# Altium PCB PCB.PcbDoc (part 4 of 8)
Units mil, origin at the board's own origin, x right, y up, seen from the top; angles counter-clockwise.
Board outline 11229.24 x 7764.43 mil, 14 copper layers (Top Layer, GND1, Signal 1, GND2, Signal 2, GND3, Singal 3, Power 1, GND4, Power 2, GND5, Power 3, GND6, Bottom Layer), stack 91.892 mil thick; 877 components, 305 nets, 2660 pads, 2851 vias.
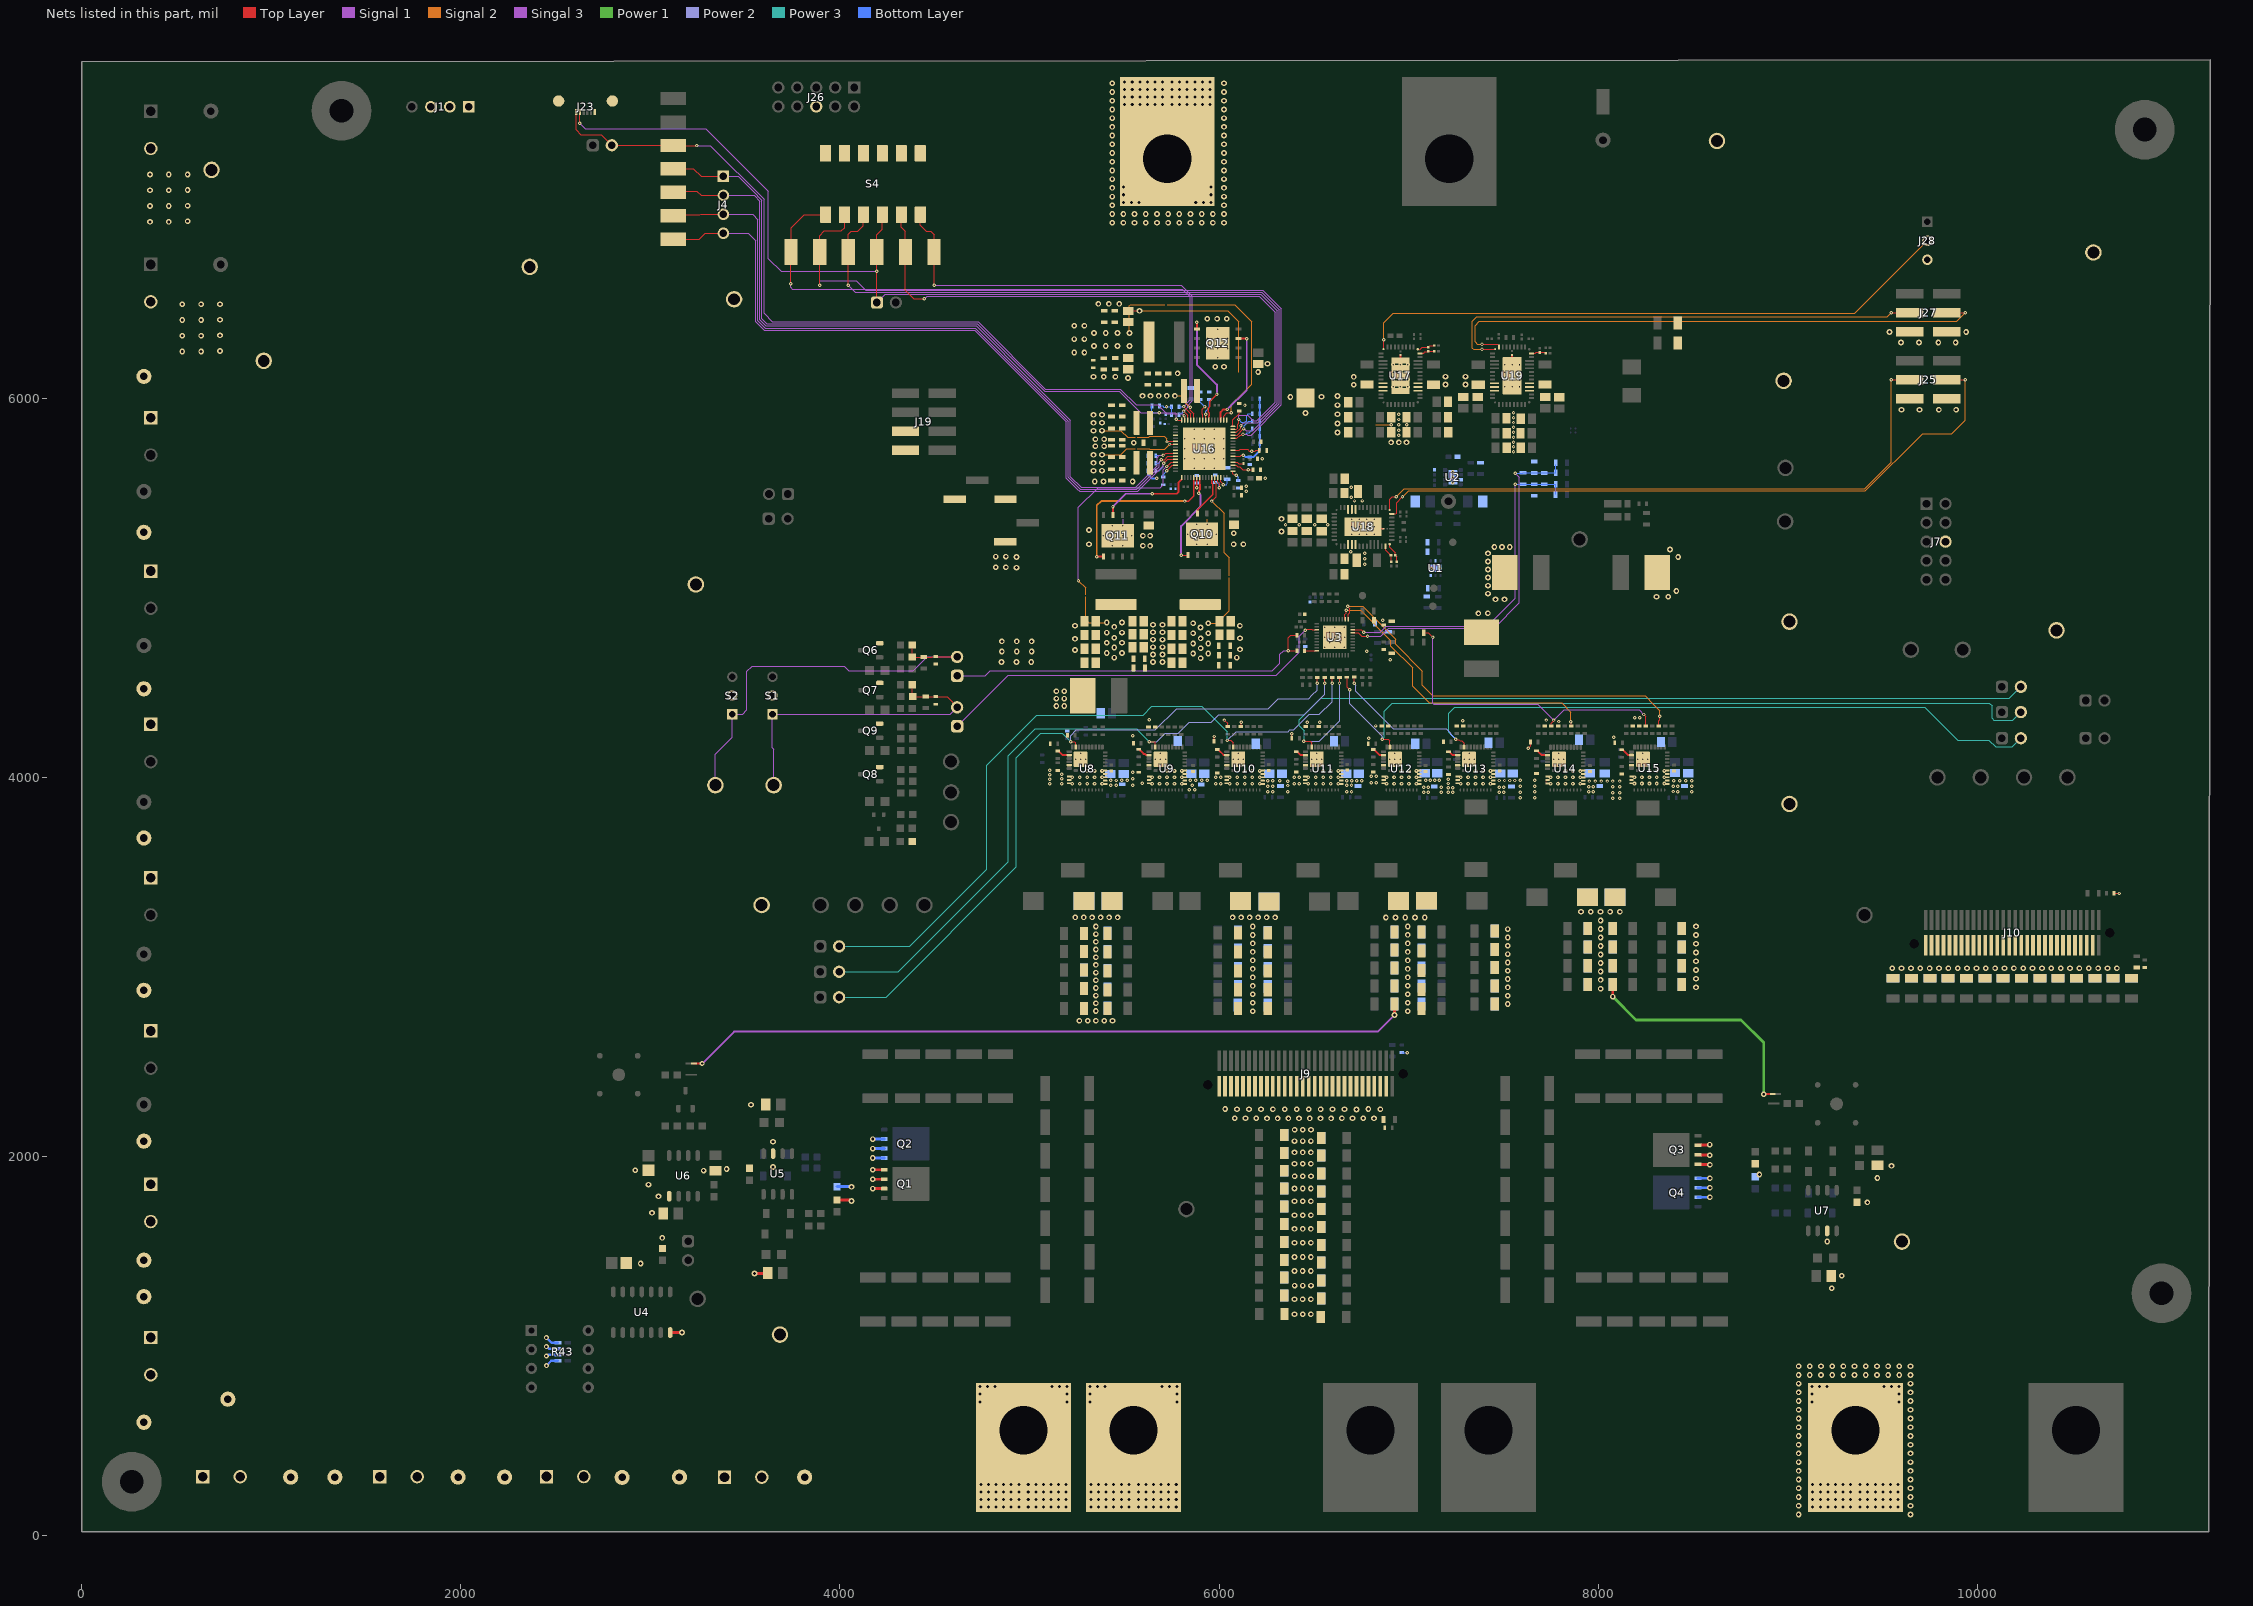
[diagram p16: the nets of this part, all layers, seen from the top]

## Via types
v1: diameter 30, hole 15, Top Layer to Bottom Layer, 1251 vias
v2: diameter 18, hole 8, Top Layer to Bottom Layer, tented both sides, 472 vias
v3: diameter 32, hole 16, Top Layer to Bottom Layer, 464 vias
v4: diameter 30, hole 15, Top Layer to Bottom Layer, tented both sides, 326 vias
v5: diameter 19.68, hole 7.87, Top Layer to Bottom Layer, 323 vias
v6: diameter 26, hole 12, Top Layer to Bottom Layer, tented both sides, 12 vias
v7: diameter 14, hole 6, Top Layer to Bottom Layer, tented both sides, 2 vias
v8: diameter 18, hole 8, Top Layer to Bottom Layer, 1 vias

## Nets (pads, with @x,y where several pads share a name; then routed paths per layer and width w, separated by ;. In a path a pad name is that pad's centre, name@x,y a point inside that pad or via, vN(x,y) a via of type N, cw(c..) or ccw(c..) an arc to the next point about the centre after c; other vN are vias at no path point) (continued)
BPWM1: R206.2 U3.1 | length 2095.7
  Top Layer w6: v2(6680.01,4902.48) 6680.01,4899.24 6689.61,4889.64 6689.61,4868.49 6681,4859.89 U3.1@6681,4832.75 ; R206.2@8320.35,4270.1 8320.35,4297.1 8325.9,4302.66 v2(8325.9,4322.06)
  Signal 2 w6: v2(6680.01,4902.48) 6758.53,4902.48 6932.22,4728.79 6932.22,4700.48 7072.8,4559.9 7072.8,4484.4 7127.96,4429.25 8247.76,4429.25 8290.66,4386.34 8325.9,4351.11 v2(8325.9,4322.06)
BPWM2: R198.2 U3.2 | length 1609.4
  Top Layer w6: U3.2@6665.25,4832.75 6664.32,4833.69 6664.32,4859.71 6669.97,4865.36 v2(6669.97,4881.79) ; v2(7856.1,4292.8) 7858.3,4290.6 R198.2@7858.3,4270.1
  Signal 2 w6: v2(6669.97,4881.79) 6746.62,4881.79 6906.93,4721.48 6906.93,4691.28 7021.38,4576.83 7021.38,4480.41 7109.49,4392.3 7807.46,4392.3 7856.1,4343.66 v2(7856.1,4292.8)
BTAO: R25.2 R201.1 R209.1 | length 1691.9
  Top Layer w6: R25.2@7079.59,4763.14 7103.7,4763.14 v2(7128.58,4738.26) ; R201.1@7753.45,4270.1 7753.45,4285.74 7766.36,4298.65 v2(7766.36,4301.9) ; v2(8240.96,4331.09) 8251.2,4320.86 R209.1@8251.2,4270.1
  Signal 1 w6: v2(7128.58,4738.26) 7128.58,4389.21 7132.09,4385.7 7682.56,4385.7 v2(7766.36,4301.9) 7820.36,4355.9 8216.16,4355.9 v2(8240.96,4331.09)
BUCK1_OUT: C309.1 C310.1 C311.1 C312.1 C313.1 C314.2 C315.2 C316.1 C398.1 J14.2 J19.5 J19.7 L11.2 NT10.2 TP49.1 | length 238.1
  Signal 2 w6: NT10.2@5295.9,4952.3 5295.9,4832.78 5312.33,4816.35 v1(5407.7,4816.35)
  other v1: 5447.4,4631.15 5407.7,4656.02 5487.8,4656.02 5447.4,4684.36 5407.7,4709.46 5487.8,4709.46 5447.4,4736.33 5407.7,4762.91 5487.8,4762.91 5447.05,4793.38 5487.8,4816.35
  other v4: 4852.6,4607.8 4931.1,4607.8 5009.6,4607.8 4854.2,4663.5 4932.7,4663.5 5011.2,4663.5 4854.2,4717 4932.7,4717 5011.2,4717
BUCK2_OUT: C319.2 C320.1 C321.1 C322.2 C323.2 C324.2 C325.1 J15.2 L12.2 NT12.2 TP51.1 | length 331.3
  Signal 2 w6: v1(5527.1,6344.1) 5527.1,6487.47 5533.13,6493.5 NT12.2@5712.57,6493.5
  other v1: 5235.8,6240.7 5289.3,6240.7 5340.04,6275.26 5402.39,6275.26 5464.75,6275.26 5527.1,6275.26 5235.85,6311.55 5289.35,6311.55 5340.04,6344.1 5402.39,6344.1 5464.75,6344.1 5235.85,6382.4 5289.35,6382.4
BUCK3_OUT: C326.2 C327.2 C328.2 J16.2 L13.2 NT13.2 TP53.1 | length 62.7
  Signal 2 w6: v4(5766.82,6012) 5816.08,6012 5819.6,6008.49 NT13.2@5819.6,5999.97
  other v4: 5596.18,6012 5638.84,6012 5681.5,6012 5724.16,6012
BUCK4_OUT: C329.1 C330.1 C331.2 C332.2 J17.2 L14.2 NT14.2 TP55.1 | length 187.9
  Signal 2 w6: v4(5382.2,5701.72) 5481.32,5701.72 5512.06,5732.45 NT14.2@5557.4,5732.45
  other v4: 5337.4,5616.68 5382.2,5617.48 5337.4,5658.8 5382.2,5659.6 5337.4,5700.92
BUCK5_OUT: C333.2 C334.2 C335.2 C396.2 J18.2 L15.2 NT15.2 TP57.1 | length 190.1
  Signal 2 w6: v4(5382.2,5828.48) 5481.62,5828.48 5517.6,5792.5 NT15.2@5557.4,5792.5
  other v4: 5337.4,5827.68 5337.4,5869.8 5382.2,5870.6 5337.4,5911.92 5382.2,5912.72
BUCK6_OUT: C301.1 C302.1 C303.1 C304.2 C305.2 C306.1 C339.1 C399.1 C400.1 C401.2 J13.2 J20.1 J21.1 J22.1 L10.2 NT8.2 TP47.1 U16.46 | length 403.4
  Top Layer w6: U16.46@6008.4,5580.87 6008.4,5558.14 v2(6022.4,5544.14)
  Signal 2 w6: v1(5943.32,4812.9) 5988.82,4812.9 6053.81,4877.89 NT8.2@6053.81,5053.82
  Bottom Layer w6: v2(6022.4,5544.14) 6040.13,5544.14 6043.65,5547.66 C339.1@6043.65,5572.45
  other v1: 5902.92,4627.7 5863.22,4652.57 5943.32,4652.57 5902.92,4680.91 5863.22,4706.01 5943.32,4706.01 5902.92,4732.88 5863.22,4759.45 5943.32,4759.45 5902.57,4789.93 5863.22,4812.9
  other v4: 4931.1,5106.1 4821.9,5107.7 4875.4,5107.7 4931.1,5162.5 4821.9,5164.1 4875.4,5164.1
BVR_EN: R20.2 U3.20 | length 64.5
  Top Layer w6: R20.2@6451.59,4667.4 6514.5,4667.4 U3.20@6515.6,4666.3
CTL1: R220.1 S4.1 TP63.1 U16.13 | length 3358.8
  Top Layer w6: v2(3740.1,6604.2) 3740.1,6769.2 TP63.1@3742.07,6771.17 3742.07,6899.37 3810.5,6967.8 S4.1@3924.11,6967.8 ; v2(5813.2,5955.83) 5813.2,5955.15 5850.92,5917.42 U16.13@5850.92,5884.02
  Singal 3 w6: v2(3740.1,6604.2) 3740.1,6585 3749.5,6575.6 5806,6575.6 5847.74,6533.86 5847.74,5990.37 v2(5813.2,5955.83)
  Bottom Layer w6: R220.1@5788.83,5955.23 5789.43,5955.83 v2(5813.2,5955.83)
CTL2: R219.1 S4.2 TP62.1 U16.60 | length 3901
  Top Layer w6: v2(3892.99,6595.3) 3892.99,6857.69 3917.6,6882.3 4007.04,6882.3 4024.11,6899.37 S4.2@4024.11,6967.8 ; U16.60@6073.37,5787.57 6094.56,5787.57 6111.09,5804.1 6117.28,5804.1 6123.09,5809.91 v2(6126.34,5809.91)
  Signal 1 w6: v2(3892.99,6595.3) 3892.99,6615.99 3896.51,6619.5 4086,6619.5 4135.3,6570.2 6230.31,6570.2 6329,6471.51 6329,5965.09 6169.16,5805.25 6151.7,5805.25 6147.04,5809.91 v2(6126.34,5809.91)
  Bottom Layer w6: v2(6126.34,5809.91) 6140.59,5809.91 6149.11,5818.43 6159.24,5818.43 6174.8,5833.99 R219.1@6174.8,5838.49
CTL3/SLPENB1: R218.1 S4.3 TP61.1 U16.61 | length 3640.9
  Top Layer w6: v2(4043.92,6595.3) 4043.92,6863.82 4059.7,6879.6 4094.83,6879.6 4124.11,6908.89 S4.3@4124.11,6967.8 ; U16.61@6073.37,5803.32 6094.75,5803.32 6128.88,5837.45 v2(6130.3,5837.45)
  Signal 1 w6: v2(4043.92,6595.3) 4080.02,6559.2 6225.76,6559.2 6318,6466.96 6318,5969.65 6177.04,5828.69 6142.3,5828.69 6133.55,5837.45 v2(6130.3,5837.45)
  Bottom Layer w6: v2(6130.3,5837.45) 6132.6,5839.74 6132.6,5853.36 6157.23,5877.99 R218.1@6174.8,5877.99
CTL4: J23.5 J24.1 S4.4 TP65.1 U16.62 | length 5591.9
  Top Layer w6: v2(2628.17,7449.22) J23.5@2628.17,7508.58 ; J24.1@4195.1,6504.5 4195.1,6770.91 TP65.1@4194.84,6771.17 4194.84,6862.54 4224.11,6891.81 S4.4@4224.11,6967.8 ; U16.62@6073.37,5819.06 6073.54,5819.24 6091.76,5819.24 6113.3,5840.78 6113.3,5852.84 v2(6115.6,5855.13)
  Signal 1 w6: J24.1@4195.1,6504.5 4238.8,6548.2 6221.2,6548.2 6307,6462.4 6307,5974.21 6203.39,5870.6 6131.07,5870.6 v2(6115.6,5855.13)
  Singal 3 w6: v2(2628.17,7449.22) 2656.49,7420.9 3292.76,7420.9 3621.5,7092.16 3621.5,6736.5 3689.2,6668.8 v2(4194.84,6668.8)
CTL5: R217.1 S4.5 TP64.1 U16.63 | length 3347.9
  Top Layer w6: S4.5@4324.11,6967.8 4324.11,6901.25 4345.76,6879.6 TP64.1@4345.76,6771.17 4343.8,6769.22 4343.8,6568.1 4388.3,6523.6 v2(4444.3,6523.6) ; U16.63@6073.37,5834.81 6091.78,5834.81 6098.6,5841.63 6098.6,5862.13 6102.92,5866.45 v2(6102.92,5887.56)
  Signal 1 w6: v2(4444.3,6523.6) 4445.88,6523.6 4459.48,6537.2 6211.46,6537.2 6296,6452.66 6296,5978.76 6198.84,5881.6 6180.26,5881.6 6152.16,5909.7 6106.43,5909.7 6102.92,5906.19 v2(6102.92,5887.56)
  Bottom Layer w6: v2@6102.96,5887.56 6118.38,5872.13 6135.82,5872.13 6145.14,5881.46 6145.14,5907.65 6154.98,5917.48 R217.1@6174.8,5917.48
CTL6/SLPENB2: R216.1 S4.6 TP66.1 U16.14 | length 2513.5
  Top Layer w6: S4.6@4424.11,6967.8 4424.11,6911.39 4455.9,6879.6 4479.62,6879.6 4496.68,6862.54 TP66.1@4496.68,6771.17 v2(4496.7,6595.3) ; v2(5813.69,5932.02) 5835.18,5910.54 U16.14@5835.18,5884.02
  Singal 3 w6: v2(4496.7,6595.3) 5801.86,6595.3 5858.74,6538.42 5858.74,5985.81 5833.74,5960.81 5833.74,5952.07 v2(5813.69,5932.02)
  Bottom Layer w6: R216.1@5788.83,5920.79 5802.45,5920.79 v2(5813.69,5932.02)
DRVH1: Q11.3 U16.33 | length 495.8
  Top Layer w10: Q11.3@5440.35,5384.05 v2(5440.35,5427.56) ; v2(5647,5495.8) 5777.73,5495.8 5785.4,5503.47 5785.4,5554.88 U16.33@5802.62,5572.09
  Signal 1 w10: v2(5440.35,5427.56) 5508.59,5495.8 v2(5647,5495.8)
DRVH2: Q12.3 U16.3 | length 542.7
  Top Layer w10: U16.3@6008.4,5884.02 6008.4,5926.2 6022.5,5940.3 v2(6043.65,5940.3) ; Q12.3@6103.3,6314.17 v2(6146.32,6314.17)
  Signal 1 w10: v2(6043.65,5940.3) 6146.32,6042.97 v2(6146.32,6314.17)
DRVH6: Q10.3 U16.43 | length 226
  Top Layer w8: Q10.3@5885.18,5391.85 5887.67,5394.35 5887.67,5413.21 5967.8,5493.34 5967.8,5544.6 5961.16,5551.24 U16.43@5961.16,5580.87
DRVL1: Q11.5 U16.37 | length 934.9
  Top Layer w6: Q11.5@5390.27,5163.9 Q11.5@5390.35,5163.97
  Top Layer w8: v2(5819.35,5457.4) 5840.04,5457.4 5866.67,5484.03 U16.37@5866.67,5580.87
  Top Layer w10: v2(5354.9,5163.9) Q11.5@5390.27,5163.9
  Signal 2 w10: v2(5354.9,5163.9) 5354.9,5433.9 5378.4,5457.4 v2(5819.35,5457.4)
DRVL2: Q12.5 U16.7 | length 620
  Top Layer w8: U16.7@5945.41,5884.02 5945.48,5884.09 5945.48,5904.82 5947.6,5906.94 5947.6,5922.74 5943.16,5927.18 5943.16,5946.88 5951.95,5955.67 5951.95,5983.64 v2(5988.98,6020.67)
  Top Layer w10: Q12.5@5883.22,6364.17 v2(5883.22,6401.34)
  Signal 1 w10: v2(5883.22,6401.34) 5883.22,6176.78 5988.98,6071.02 v2(5988.98,6020.67)
DRVL6: Q10.5 U16.39 | length 494
  Top Layer w6: v2(5799.73,5171.7) Q10.5@5835.1,5171.7
  Top Layer w10: v2(5892.6,5498.53) 5894.13,5500.06 5894.13,5512.78 5899.42,5518.07 5899.42,5544.91 5898.17,5546.16 U16.39@5898.17,5580.87
  Signal 1 w10: v2(5799.73,5171.7) 5799.73,5325.31 5902.92,5428.5 5902.92,5488.21 v2@5893.24,5497.89
EN1_YES_1: J25.3 U18.1 | length 3315
  Top Layer w6: U18.1@6900.12,5410 6900.71,5410.6 6900.71,5466.21 6914.27,5479.77 v2(6935.63,5479.77) ; v2(9546.3,6096.9) J25.3@9643.46,6096.9
  Signal 2 w6: v2(6935.63,5479.77) 6977.56,5521.7 9405.6,5521.7 9546.3,5662.4 v2(9546.3,6096.9)
EN1_YES_2: J27.3 U19.1 | length 2590.1
  Top Layer w6: v2(7387.16,6257.85) 7387.41,6258.1 7456.12,6258.1 U19.1@7456.37,6258.34 ; v2(9546.3,6450.6) J27.3@9643.46,6450.6
  Signal 2 w6: v2(7387.16,6257.85) 7342.95,6257.85 7336.2,6264.6 7336.2,6405.7 7358.8,6428.3 9524,6428.3 v2(9546.3,6450.6)
EN1_YES_3: J28.2 U17.1 | length 3186.5
  Top Layer w6: U17.1@6867.92,6258.34 6868.16,6258.58 6868.16,6308.06 v2(6868.4,6308.3)
  Signal 2 w6: v2(6868.4,6308.3) 6868.4,6397.1 6919.9,6448.6 9354.9,6448.6 J28.2@9736.5,6830.2
EN2_YES_1: J25.4 U18.46 | length 3571.2
  Top Layer w6: U18.46@6911.43,5389.63 6933.01,5389.63 6936.52,5393.15 6936.52,5448.58 v2(6967.71,5479.77) ; J25.4@9838.34,6096.9 v2(9935.5,6096.9)
  Signal 2 w6: v2(6967.71,5479.77) 6970.29,5479.77 7001.23,5510.7 9410.16,5510.7 9712.46,5813 9864.2,5813 9935.5,5884.3 v2(9935.5,6096.9)
EN2_YES_2: J27.4 U19.46 | length 2942.1
  Top Layer w6: v2(7387.16,6284.84) 7471.3,6284.84 7474.82,6281.32 7474.82,6271.58 U19.46@7476.74,6269.66 ; J27.4@9838.34,6450.6 v2(9936.6,6450.6)
  Signal 2 w6: v2(7387.16,6284.84) 7361.86,6284.84 7350.3,6296.4 7350.3,6382.47 7373.53,6405.7 9891.7,6405.7 v2(9936.6,6450.6)
EN_VOUT_A: J2.1 U3.13 | length 2159.3
  Top Layer w6: v2(6454.62,4774.9) 6457.86,4774.9 6463.1,4780.14 6488.15,4780.14 6490.65,4777.63 U3.13@6515.65,4777.63
  Singal 3 w6: J2.1@4618.2,4269 4886.74,4537.54 6301.05,4537.54 6423.54,4660.02 6423.54,4743.82 v2(6454.62,4774.9)
EN_VOUT_A_N: C17.1 J2.2 R22.1 R138.1 R142.2 S1.1 TP9.1 | length 1690.3
  Top Layer w6: R142.2@4382.4,4487.96 4382.4,4425.6 R22.1@4453.15,4425.6 C17.1@4505.5,4425.6 4565.8,4425.6 4618.2,4373.2 J2.2@4618.2,4369
  Singal 3 w6: TP9.1@3650.3,3958.07 3650.3,4148.7 3644.2,4154.8 S1.1@3644.2,4332.7 4581.9,4332.7 J2.2@4618.2,4369
EN_VOUT_B: J3.1 R20.1 R21.1 | length 1995.1
  Top Layer w6: R21.1@6411.3,4748.7 6377.69,4748.7 6365.32,4736.33 v2(6365.32,4667.4) R20.1@6411.59,4667.4
  Singal 3 w6: J3.1@4618.2,4534.8 4767.2,4534.8 4794.14,4561.74 6280.44,4561.74 6321.09,4602.39 6321.09,4648.11 6340.38,4667.4 v2(6365.32,4667.4)
EN_VOUT_B_N: C18.1 J3.2 R23.1 R137.1 R141.2 S2.1 TP10.1 | length 2163
  Top Layer w6: R141.2@4382.4,4697.9 R137.1@4382.4,4634.19 4382.69,4633.9 R23.1@4442.9,4633.9 4485.45,4633.9 4486.35,4634.8 J3.2@4618.2,4634.8
  Singal 3 w6: TP10.1@3342.95,3958.07 3342.95,4122.5 3432.2,4211.74 S2.1@3432.2,4332.7 3486.8,4332.7 3509.4,4355.3 3509.4,4559.2 3536.3,4586.1 4022.5,4586.1 4047.6,4561 4387.8,4561 4461.6,4634.8 J3.2@4618.2,4634.8
FB3: NT13.1 U16.12 | length 126.2
  Top Layer w6: v2(5847.74,5952.17) 5847.74,5936.16 5866.67,5917.23 U16.12@5866.67,5884.02
  Signal 2 w6: NT13.1@5819.6,5989.97 5819.6,5979.1 5846.52,5952.17 v2(5847.74,5952.17)
FB4: NT14.1 U16.23 | length 215.4
  Top Layer w6: v7(5740.14,5756.82) 5740.53,5756.43 5769.86,5756.43 U16.23@5770.22,5756.07
  Signal 2 w6: NT14.1@5567.4,5732.45 5631.94,5732.45 5634.59,5729.8 5713.12,5729.8 v7(5740.14,5756.82)
FB5: NT15.1 U16.22 | length 228.6
  Top Layer w6: v7(5725.2,5769.28) 5726.82,5769.28 5729.37,5771.82 U16.22@5770.22,5771.82
  Signal 2 w6: NT15.1@5567.4,5792.5 5628.5,5792.5 5635,5799 5712.1,5799 5725.2,5785.9 v7(5725.2,5769.28)
FBVOUT1: NT10.1 U16.29 | length 1134
  Top Layer w6: v2(5723.59,5639.56) 5725.63,5639.56 5747.29,5661.23 5769.86,5661.23 U16.29@5770.22,5661.58
  Signal 1 w6: v2(5258.3,5036.7) 5258.3,5424.7 5361.54,5527.94 5690.39,5527.94 5705.84,5543.39 5705.84,5621.82 v2(5723.59,5639.56)
  Signal 2 w6: v2(5258.3,5036.7) 5295.9,4999.1 NT10.1@5295.9,4962.3
FBVOUT2: NT12.1 U16.2 | length 1079.3
  Top Layer w6: U16.2@6024.15,5884.02 6024.15,5905.74 6041.71,5923.3 v2(6063.57,5923.3)
  Signal 2 w6: NT12.1@5725.57,6493.5 6083.7,6493.5 6173.3,6403.9 6173.3,6073.72 6063.57,5963.99 v2(6063.57,5923.3)
FBVOUT6: NT8.1 U16.44 | length 568.2
  Top Layer w6: v2(5961.16,5457.4) 5984.41,5480.65 5984.41,5548.97 5976.91,5556.47 U16.44@5976.91,5580.87
  Signal 2 w6: v2(5961.16,5457.4) 6026.7,5391.86 6026.7,5184.7 6053.81,5157.59 NT8.1@6053.81,5063.82
GND: C1.2 C2.2 C3.2 C4.2 C5.2 C6.2 C7.2 C8.2 C9.2 C11.2 C13.2 C14.2 C15.2 C16.2 C17.2 C18.2 C19.2 C21.2 C22.2 C23.2 C24.2 C25.2 C26.2 C27.1 C28.2 C29.2 C30.1 C31.1 C32.2 C33.2 C34.2 C35.2 C36.2 C37.2 C38.2 C39.2 C40.2 C41.2 C42.2 C43.2 C44.2 C45.2 C46.2 C47.2 C48.2 C49.2 C50.2 C51.2 C52.2 C53.2 C54.2 C55.2 C56.2 C57.2 C58.2 C59.2 C60.2 C61.2 C62.2 C63.2 C64.2 C65.2 C66.2 C67.2 C68.2 C69.2 C70.2 C71.2 C72.2 C73.2 C74.2 C75.2 C76.2 C77.2 C78.2 C79.2 C80.2 C81.2 C83.1 C84.1 C85.1 C86.1 C87.2 C88.2 C89.2 C90.2 C91.2 C92.2 C93.2 C94.2 C95.2 C96.2 C97.2 C98.2 C99.2 C100.2 C101.2 C102.2 C103.2 C104.2 C105.2 C106.2 C107.2 C108.2 C109.2 C110.2 C111.2 C112.2 C113.2 C114.2 C115.2 C116.2 C117.2 C118.2 C119.2 C120.2 C121.2 C122.2 C123.2 C124.2 C125.2 C126.2 C127.2 C128.2 C129.2 C130.2 C131.2 C132.2 C133.2 C134.2 C135.2 C136.2 C137.2 C138.2 C139.2 C140.2 C141.2 C142.2 C143.2 C144.2 C145.2 C146.2 C147.2 C148.2 C149.2 C150.2 C151.2 C152.2 C153.2 C154.2 C155.2 C156.2 C157.2 C158.2 C159.2 C160.2 C161.2 C162.2 C163.2 C164.2 C165.2 C166.2 C167.2 C168.2 C169.2 C170.2 C172.2 C173.2 C174.2 C175.2 C176.2 C177.2 C178.2 C179.2 C180.2 C181.2 C182.1 C183.2 C184.2 C185.1 C188.2 C189.2 C190.2 C191.2 C192.2 C193.2 C194.2 C195.2 C196.2 C197.2 C198.2 C199.1 C200.2 C201.1 C204.2 C205.2 C206.2 C207.2 C208.2 C209.2 C210.2 C211.2 C212.2 C213.2 C214.2 C215.2 C216.1 C217.1 C220.2 C221.2 C222.2 C223.2 C224.2 C225.2 C226.2 C227.2 C228.2 C229.2 C230.1 C231.2 C232.2 C233.1 C236.2 C237.2 C238.2 C239.2 C240.2 C241.2 C242.2 C243.2 C244.2 C245.2 C246.2 C247.2 C248.1 C249.1 C252.2 C253.2 C254.2 C255.2 C256.2 C257.2 C258.2 C259.2 C260.2 C261.2 C262.2 C263.2 C264.1 C265.1 C268.2 C269.2 C270.2 C271.2 C272.2 C273.2 C274.2 C275.2 C276.2 C277.2 C278.1 C279.1 C280.2 C281.2 C284.2 C285.2 C286.2 C287.2 C288.2 C289.2 C290.2 C291.2 C292.2 C293.2 C294.2 C295.1 C296.2 C297.1 C299.2 C301.2 C302.2 C303.2 C304.1 C305.1 C306.2 C307.2 C309.2 C310.2 C311.2 C312.2 C313.2 C314.1 C315.1 C316.2 C317.2 C319.1 C320.2 C321.2 C322.1 C323.1 C324.1 C325.2 C326.1 C327.1 C328.1 C329.2 C330.2 C331.1 C332.1 C333.1 C334.1 C335.1 C336.2 C337.2 C338.2 C339.2 C340.2 C341.2 C342.2 C343.2 C344.2 C345.2 C346.2 C347.2 C348.2 C349.2 C350.2 C351.2 C352.2 C353.2 C354.2 C355.2 C356.2 C357.2 C358.2 C359.2 C360.2 C361.2 C362.2 C363.2 C364.2 C365.2 C366.2 C367.2 C368.2 C370.2 C371.2 C372.2 C373.2 C374.2 C375.2 C376.2 C377.2 C378.2 C379.2 C380.2 C381.2 C383.2 C384.2 C385.2 C386.2 C387.2 C388.2 C390.2 C391.2 C392.2 C393.2 C394.2 C395.2 C396.1 C397.2 C398.2 C399.2 C400.2 C401.1 J7.6 J9.124 J9.126 J9.128 J9.130 J9.132 J9.134 J9.136 J9.138 J9.140 J9.142 J9.144 J9.146 J9.148 J9.150 J9.152 J9.154 J9.156 J9.158 J9.160 J9.162 J9.164 J9.166 J9.168 J9.170 J9.172 J9.174 J9.176 J9.178 J9.180 J10.124 J10.126 J10.128 J10.130 J10.132 J10.134 J10.136 J10.138 J10.140 J10.142 J10.144 J10.146 J10.148 J10.150 J10.152 J10.154 J10.156 J10.158 J10.160 J10.162 J10.164 J10.166 J10.168 J10.170 J10.172 J10.174 J10.176 J10.178 J10.180 J13.1 J14.1 J15.1 J16.1 J17.1 J18.1 J23.1 J23.MP1 J23.MP2 J25.5 J25.6 J26.6 J27.5 J27.6 J28.3 J30.2 J31.2 J33.1 J34.1 J35.1 J36.1 J37.1 NT5.1 NT6.1 NT7.2 NT9.2 NT11.2 NT16.1 NT17.2 NT18.2 NT19.2 Q1.1 Q1.2 Q1.3 Q2.1 Q2.2 Q2.3 Q3.1 Q3.2 Q3.3 Q4.1 Q4.2 Q4.3 Q6.2 Q7.2 Q8.2 Q9.2 Q10.9 Q11.9 Q12.9 R6.1 R13.1 R15.1 R16.1 R19.1 R33.1 R37.1 R43.5 R43.6 R43.7 R43.8 R76.2 R79.1 R80.1 R81.2 R116.1 R120.2 R123.1 R124.1 R127.1 R144.1 R147.1 R149.1 R155.1 R157.1 R163.1 R165.1 R171.1 R173.1 R179.1 R181.1 R187.1 R189.1 R195.1 R197.1 R203.1 R205.1 R211.2 R212.2 R213.2 S1.2 S2.2 S4.7 S4.8 S4.9 S4.10 S4.11 S4.12 T2.1 T5.1 T6.1 T8.1 TP5.1 TP7.1 TP17.1 TP18.1 TP21.1 TP22.1 TP23.1 TP24.1 TP25.1 TP26.1 TP27.1 TP48.1 TP50.1 TP52.1 TP54.1 TP56.1 TP58.1 TP68.1 TP77.1 TP81.1 TP83.1 TP84.1 TP85.1 TP86.1 TP87.1 U1.3 U1.5 U1.7 U2.3 U2.9 U3.41@6610.14,4738.26 U4.7 U5.3 U6.1 U7.3 U8.2 U8.5 U8.7 U8.8 U8.9 U8.20 U8.21 U8.22 U8.23 U8.24@5398.65,4035.27 U8.40@5269.71,4095.31 U9.2 U9.5 U9.7 U9.8 U9.9 U9.20 U9.21 U9.22 U9.23 U9.24@5819.89,4035.27 U9.40@5690.95,4095.31 U10.2 U10.5 U10.7 U10.8 U10.9 U10.20 U10.21 U10.22 U10.23 U10.24@6230.04,4035.27 U10.40@6101.11,4095.31 U11.2 U11.5 U11.7 U11.8 U11.9 U11.20 U11.21 U11.22 U11.23 U11.24@6644.44,4035.27 U11.40@6515.5,4095.3 U12.2 U12.5 U12.7 U12.8 U12.9 U12.20 U12.21 U12.22 U12.23 U12.24@7057.1,4035.27 U12.40@6928.16,4095.3 U13.2 U13.5 U13.7 U13.8 U13.9 U13.20 U13.21 U13.22 U13.23 U13.24@7447.79,4035.27 U13.40@7318.85,4095.3 U14.2 U14.5 U14.7 U14.8 U14.9 U14.20 U14.21 U14.22 U14.23 U14.24@7921.87,4034.87 U14.40@7792.94,4094.91 U15.2 U15.5 U15.7 U15.8 U15.9 U15.20 U15.21 U15.22 U15.23 U15.24@8364.9,4035.59 U15.40@8235.96,4095.62 U16.1 U16.52 U16.65 U17.10 U17.11 U17.12 U17.27 U17.28 U17.29 U17.47 U17.48 U17.49 U17.50 U17.51 U18.10 U18.11 U18.12 U18.27 U18.28 U18.29 U18.47-48-49-50-51 U19.10 U19.11 U19.12 U19.27 U19.28 U19.29 U19.47-48-49-50-51 | length 8415.7
  Top Layer w6: C320.2@5521.8,6460.39 v4(5580.37,6460.39) ; C216.1@5974.05,4190.54 v2@5974.05,4215.08 ; v2(6027.89,4301.95) 6044.96,4284.88 R165.1@6044.96,4267.02 ; U16.52@6073.37,5661.58 6096.97,5661.58 6103.3,5655.25 C352.2@6128.7,5655.25 ; C217.1@6116.53,4267.16 v2(6116.53,4290.19) ; C230.1@6383.84,4205.16 6384.04,4205.36 6384.04,4229.91 v2(6384.24,4230.12) ; R173.1@6464.55,4267.34 R173.1@6464.74,4267.16 ; C233.1@6531.23,4267.16 C233.1@6531.27,4267.2 ; v5(6818.92,5320.73) U18.47-48-49-50-51@6828.76,5310.89 ; C264.1@7183.28,4186.21 C264.1@7183.35,4186.15 ; U19.47-48-49-50-51@7545.53,6177.25 v5(7545.64,6177.14) ; v2(7630.5,4153.9) 7643.31,4166.71 C278.1@7643.31,4186.06 ; 7724.79,3976.6 7725.3,3977.11 ; 7790.49,3976.6 7790.58,3976.7 ; C297.1@8225.58,4270.16 C297.1@8225.63,4270.1 ; C13.2@10721.64,3387.33 10722.04,3386.93 v2(10748.24,3386.93)
  Top Layer w10: NT5.1@3230.02,2489.38 3272.61,2489.38 v6(3273.18,2489.95) ; C184.2@5148.25,4139.23 5152.75,4139.23 5175.02,4116.96 U8.2@5209.67,4116.96 ; C198.2@5576.35,4148.13 5580.85,4148.13 5583.35,4145.63 5583.35,4141.74 5601.96,4123.13 5609.38,4123.13 5614.72,4117.79 5630.09,4117.79 U9.2@5630.91,4116.96 ; C215.2@5990.53,4146.22 5993.03,4143.72 5997.53,4143.72 6023.46,4117.79 6040.24,4117.79 U10.2@6041.07,4116.96 ; C232.2@6407.63,4135.03 6412.13,4135.03 6430.2,4116.96 U11.2@6455.46,4116.96 ; C247.2@6813.67,4145.96 6816.17,4143.46 6820.67,4143.46 6847.17,4116.96 U12.2@6868.12,4116.96 ; U18.47-48-49-50-51@6828.76,5310.89 NT17.2@6867.3,5310.89 ; v5@6957.21,6177.16 NT16.1@6957.21,6227.02 ; C263.2@7210.42,4134.91 7214.92,4134.91 7232.87,4116.96 U13.2@7258.81,4116.96 ; U19.47-48-49-50-51@7545.53,6177.25 NT18.2@7545.53,6228.47 ; C281.2@7674.72,4139.56 7679.22,4139.56 7702.22,4116.57 U14.2@7732.9,4116.57 ; C294.2@8125.2,4145.38 8129.7,4145.38 8157.31,4117.77 8175.43,4117.77 U15.2@8175.92,4117.28 ; v1(8873.28,2327.87) 8875.12,2329.7 NT6.1@8920.8,2329.7
  Top Layer w15: C31.1@2873.1,1436.6 C31.1@2874.9,1434.8 ; C26.2@2989.9,1926.13 C26.2@2990.23,1926.46 ; v4(3042.7,1789) v4@3043.25,1789.55 ; v4(3062.2,1569.9) v4@3062.77,1569.33 ; R116.1@3062.77,1514.63 R116.1@3063.33,1514.06 ; C29.2@3063.94,1701.8 C29.2@3066.64,1699.1 ; U6.1@3098.61,1789.55 U6.1@3099.16,1790.09 ; U4.7@3104.4,1070.52 3104.74,1070.86 3166.46,1070.86 v4(3166.8,1071.2) ; C27.1@3522.1,1938.65 C27.1@3523.55,1937.2 ; v4(3549.2,1381.7) 3617.08,1381.7 R76.2@3619.52,1384.14 ; R79.1@3984.32,1769.97 4051.5,1769.97 4056.46,1765 v4(4060.52,1765) ; v1(4172.95,1829.75) Q1.3@4234.2,1829.75 ; v1(4172.95,1879.75) Q1.2@4234.2,1879.75 ; v1(4172.95,1929.75) Q1.1@4234.2,1929.75 ; v4@6925.89,2747.8 C240.2@6925.89,2803.92 ; v1(8076.7,2842.79) C147.2@8076.7,2907.17 ; Q3.1@8526.69,1958.71 8528.26,1957.14 8587.59,1957.14 v1(8589.17,1955.56) ; Q3.2@8526.69,2008.71 8528.26,2007.14 8587.13,2007.14 v1(8588.7,2005.56) ; Q3.3@8526.69,2058.71 8528.26,2060.28 8587.12,2060.28 v1(8588.7,2061.86) ; C30.1@9365.8,1757.2 C30.1@9366.4,1756.6 ; R120.2@9472.77,1952.24 R120.2@9476.09,1955.56
  Signal 1 w10: v6(3273.18,2489.95) 3441.46,2658.24 6836.32,2658.24 v4@6925.89,2747.8
  Signal 2 w6: v5(5493.1,5326.3) v5@5493.3,5326.49 ; v4(5580.37,6460.39) 6046.08,6460.39 6103.7,6402.77 NT11.2@6103.7,6136.5 ; v5(5937.93,5334.1) NT19.2@5937.93,5362 ; NT7.2@6827.7,5859.51 v2(6908.56,5859.51)
  Singal 3 w6: v5@5493.3,5326.49 NT9.2@5493.3,5362
  Power 1 w15: v1(8076.7,2842.79) 8199.39,2720.1 8753.7,2720.1 8873.28,2600.52 v1(8873.28,2327.87)
  Bottom Layer w6: C11.2@6964.5,2547.3 6964.55,2547.35 v2(6992.8,2547.4) v2(6992.8,2547.4)
  Bottom Layer w12: v6(2451.3,947.2) 2455.09,947.2 2461.24,953.35 R43.6@2512.91,953.35 ; v6(2451.3,996) 2455.09,996 2466.24,984.85 R43.7@2512.91,984.85 ; v6(2451.3,1043.5) 2478.46,1016.34 R43.8@2512.91,1016.34 ; v6(2451.87,896.1) 2477.63,921.86 R43.5@2512.91,921.86
  Bottom Layer w15: R80.1@3984.33,1840.39 4059.32,1840.39 v4(4060.52,1839.18) ; v1(4172.95,1991.03) Q2.1@4234.2,1991.03 ; v1(4172.95,2041.03) Q2.2@4234.2,2041.03 ; v1(4172.95,2091.03) Q2.3@4234.2,2091.03 ; Q4.3@8526.69,1784.31 v1(8589.17,1784.31) ; Q4.2@8526.69,1834.31 v1(8589.17,1834.31) ; Q4.1@8526.69,1884.31 v1(8589.17,1884.31)
  other v1: 9057.5,111.1 9647.8,111.1 9057.5,157.09 9647.8,157.09 9057.5,203.09 9647.8,203.09 9057.5,249.08 9647.8,249.08 9057.5,295.07 9647.8,295.08 9057.5,341.07 9647.8,341.07 9057.5,387.06 9647.8,387.06 9057.5,433.06 9647.8,433.06 9057.5,479.05 9647.8,479.05 9057.5,525.04 9647.8,525.04 9057.5,571.04 9647.8,571.04 9057.5,617.03 9647.8,617.03 9057.5,663.02 9647.8,663.02 9057.5,709.02 9647.8,709.02 9057.5,755.01 9647.8,755.01 9057.5,801.01 9647.8,801.01 9057.5,847 9116.53,847 9175.56,847 9234.59,847 9293.62,847 9352.65,847 9411.68,847 9470.71,847 9529.74,847 9588.77,847 9647.8,847 9057.5,892.99 9116.53,892.99 9175.56,892.99 9234.59,892.99 9293.62,892.99 9352.65,892.99 9411.68,892.99 9470.71,892.99 9529.74,892.99 9588.77,892.99 9647.8,892.99 6397.95,1167.48 6441.79,1167.48 6484.25,1167.48 6397.95,1246.4 6441.1,1246.4 6484.25,1246.4 6398.64,1318.3 6441.79,1318.3 6484.94,1318.3 6397.95,1395.4 6441.1,1395.4 6484.25,1395.4 6398.25,1469.4 6441.4,1469.4 6484.55,1469.4 6398.25,1544.33 6441.4,1544.33 6484.55,1544.33 6398.25,1617.4 6441.4,1617.4 6484.55,1617.4 6398.25,1689.6 6441.4,1689.6 6484.55,1689.6 6398.25,1763.6 6441.4,1763.6 6484.55,1763.6 6398.25,1830.21 6441.4,1830.21 6484.55,1830.21 6398.64,1895.14 6441.79,1895.14 6484.94,1895.14 6398.25,1961.42 6441.4,1961.42 6484.55,1961.42 6398.25,2021.01 6441.4,2021.01 6484.55,2021.01 6398.25,2080.59 6441.4,2080.59 6484.55,2080.59 6398.64,2140.18 6441.79,2140.18 6484.94,2140.18 6252.57,2200.5 6309.03,2200.5 6365.49,2200.5 6421.95,2200.5 6478.4,2200.5 6534.86,2200.5 6591.32,2200.5 6817.15,2200.5 6083.2,2201 6196.12,2201 6139.66,2201.5 6647.78,2201.5 6704.23,2201.5 6760.69,2201.5 6724.86,2247.7 6094.94,2248.7 6157.93,2248.7 6220.93,2248.7 6283.92,2248.7 6346.91,2248.7 6409.9,2248.7 6472.89,2248.7 6535.89,2248.7 6598.88,2248.7 6661.87,2248.7 6850.85,2248.7 6031.95,2249.7 6787.85,2249.7 6177.48,2765.38 6995.31,2765.74 5350.2,2766.86 7523.3,2803.92 5350.2,2807.43 6177.48,2810.15 6995.31,2810.2 5350.2,2848.01 7523.3,2847.78 6177.48,2854.93 6995.31,2854.98 8013.2,2884.7 5350.2,2888.58 8516.5,2891.47 7523.3,2891.65 6177.48,2899.7 6995.31,2899.75 5350.2,2929.15 8012.86,2931 7523.3,2935.51 8516.5,2937.46 6177.48,2944.47 6995.31,2944.52 5350.2,2969.5 8012.86,2975.78 7523.3,2979.38 8516.5,2983.46 6177.48,2989.25 6995.31,2989.3 9551.14,2992.33 9600.52,2992.33 9649.9,2992.33 9699.28,2992.33 9748.66,2992.33 9798.04,2992.33 9847.42,2992.33 9896.8,2992.33 9946.18,2992.33 9995.56,2992.33 10044.94,2992.33 10094.32,2992.33 10143.7,2992.33 10193.08,2992.33 10242.46,2992.33 10291.84,2992.33 10341.22,2992.33 10390.6,2992.33 10439.98,2992.33 10489.36,2992.33 10538.74,2992.33 10588.12,2992.33 10637.5,2992.33 10686.88,2992.33 10736.26,2992.33 5350.2,3010.3 8012.86,3020.55 7523.3,3023.24 8516.5,3029.45 6177.48,3034.02 6995.31,3034.07 5350.2,3050.87 8012.86,3065.32 7523.3,3067.11 8516.5,3075.44 6177.48,3078.79 6995.31,3078.84 5350.2,3091.44 8012.86,3110.1 7523.3,3110.97 8516.5,3121.44 6177.48,3123.57 6995.31,3123.62 5350.2,3132.02 7523.3,3154.83 8012.86,3154.87 8516.5,3167.43 6177.48,3168.34 6995.31,3168.39 5350.2,3172.59 7523.3,3198.7 8012.86,3199.64 5350.2,3213.16 6177.48,3213.11 6995.31,3213.16 8516.5,3213.42 8012.86,3244.42 5436.2,6925.31 5495.23,6925.31 5554.26,6925.31 5613.29,6925.31 5672.32,6925.31 5731.35,6925.31 5790.38,6925.31 5849.41,6925.31 5908.44,6925.31 5967.47,6925.31 6026.5,6925.31 5436.2,6971.3 5495.23,6971.3 5554.26,6971.3 5613.29,6971.3 5672.32,6971.3 5731.35,6971.3 5790.38,6971.3 5849.41,6971.3 5908.44,6971.3 5967.47,6971.3 6026.5,6971.3 5436.2,7017.29 6026.5,7017.3 5436.2,7063.29 6026.5,7063.29 5436.2,7109.28 6026.5,7109.28 5436.2,7155.28 6026.5,7155.28 5436.2,7201.27 6026.5,7201.27 5436.2,7247.26 6026.5,7247.26 5436.2,7293.26 6026.5,7293.26 5436.2,7339.25 6026.5,7339.25 5436.2,7385.24 6026.5,7385.24 5436.2,7431.24 6026.5,7431.24 5436.2,7477.23 6026.5,7477.23 5436.2,7523.23 6026.5,7523.23 5436.2,7569.22 6026.5,7569.22 5436.2,7615.21 6026.5,7615.21 5436.2,7661.21 6026.5,7661.21
  other v2: 8076.92,3888.32 8114.65,3888.32 7588.1,3891.41 7666.2,3891.99 8076.92,3918.91 8114.65,3918.91 7079.29,3920.81 7102.69,3920.57 7172.92,3920.57 7209.6,3920.57 7233.86,3920.81 7479.08,3920.81 7502.48,3920.57 7588.1,3922.01 6362.74,3922.55 7666.2,3922.59 7949.77,3923.25 7973.17,3923 8493.67,3923.25 6257.14,3923.84 6282.89,3923.84 6673.12,3923.52 6698.87,3923.52 8396,3924.77 8419.4,3924.52 5843.4,3934.9 5872.05,3934.9 7209.6,3943.91 7233.86,3943.91 7079.28,3948.16 7102.68,3947.91 7172.92,3948.16 7479.07,3948.16 7502.47,3947.91 7973.16,3950.35 8076.92,3949.51 8114.65,3949.51 7949.76,3950.6 6257.14,3952.34 6282.89,3952.34 8395.99,3952.12 8419.39,3951.87 7588.1,3952.6 7666.2,3953.19 8493.98,3953.19 6362.74,3956.45 5428.73,3957.3 5457.38,3957.3 5544.64,3956.99 5859.24,3956.99 6673.12,3956.99 6698.87,3956.99 5106.6,3966.37 5169.73,3966.37 5983.41,3966.52 6009.16,3966.52 6397.1,3966.52 6422.85,3966.52 7209.6,3967.25 5595.02,3967.82 6802.72,3971.74 6828.48,3971.74 6363.36,3979.99 7952.75,3980.11 7984.43,3980.11 8016.11,3980.11 8047.79,3980.11 8076.92,3980.11 8114.65,3980.11 6257.14,3980.84 6282.89,3980.84 6321.09,3980.84 8398.62,3981.33 8430.28,3981.33 8463.04,3981.33 8493.67,3981.33 6673.12,3981.64 6699.77,3981.64 6726.41,3981.64 6753.06,3981.64 5428.73,3983.39 5457.38,3983.07 7479.07,3982.96 7505.97,3982.96 7532.86,3982.96 7559.75,3982.96 7588.1,3983.2 5486.03,3983.73 5514.68,3983.73 5847.86,3983.91 5877.85,3983.91 5907.84,3983.91 5937.83,3983.91 7666.2,3983.78 7090.76,3984.79 7114.18,3984.79 7137.6,3984.79 7161.02,3984.79 5106.6,3989.57 5169.73,3991.39 7209.6,3990.58 5544.64,3991.85 5983.41,3999.98 6009.16,3999.98 6397.1,3999.98 6422.85,3999.98 6802.72,4005.2 6828.48,4005.2 5106.6,4012.78 5169.73,4016.42 5544.64,4026.71 5106.6,4035.99 6789.58,4206.28 8081.25,4211.04 5974.17,4215.19 5545.35,4218.6 6827.41,4270.54 6464.55,4290.4 6531.27,4289.99 7793.1,4294.1 7285.27,4297.67 7725.07,4301.94 5632.82,4303.93 8219.28,4313.35 8192.48,4313.58 6902.12,4620.06 6778.49,4664.09 6557.75,4685.11 6661.43,4685.11 6582.95,4709.95 6638.69,4709.95 6638.45,4763.14 6582.95,4765.26 6557.78,4790.86 6661.43,4790.86 6863.09,4829.07 6768.69,5124.06 6768.69,5152.77 6768.69,5180.79 6694.4,5189.33 6423.54,5331.52 6350.64,5332.58 6503.95,5332.58 6573.35,5332.6 6714.45,5457.63 6754.52,5457.63 6696.45,5477.53 6143.31,5507.94 6696.45,5530.14 6143.31,5535.87 6244.07,5578.47 6228.86,5679.26 7553.56,5716.92 7553.56,5742.67 7553.56,5768.41 7553.56,5794.16 6948.6,5803.32 7553.56,5819.91 6948.6,5831.41 7553.56,5845.66 6948.6,5859.51 6989.31,5859.51 7553.56,5871.4 6948.6,5887.6 7553.56,5897.15 6948.6,5915.7 7553.56,5922.9 6136.72,5963.33
  other v3: 4743.43,150.2 4783.43,150.2 4823.43,150.2 4863.43,150.2 4903.43,150.2 4943.43,150.2 4993.43,150.2 5033.43,150.2 5073.43,150.2 5113.43,150.2 5153.43,150.2 5193.43,150.2 5324.14,150.2 5364.14,150.2 5404.14,150.2 5444.14,150.2 5484.14,150.2 5524.14,150.2 5574.14,150.2 5614.14,150.2 5654.14,150.2 5694.14,150.2 5734.14,150.2 5774.14,150.2 9131.9,150.2 9171.9,150.2 9211.9,150.2 9251.9,150.2 9291.9,150.2 9331.9,150.2 9381.9,150.2 9421.9,150.2 9461.9,150.2 9501.9,150.2 9541.9,150.2 9581.9,150.2 4743.43,190.2 4783.43,190.2 4823.43,190.2 4863.43,190.2 4903.43,190.2 4943.43,190.2 4993.43,190.2 5033.43,190.2 5073.43,190.2 5113.43,190.2 5153.43,190.2 5193.43,190.2 5324.14,190.2 5364.14,190.2 5404.14,190.2 5444.14,190.2 5484.14,190.2 5524.14,190.2 5574.14,190.2 5614.14,190.2 5654.14,190.2 5694.14,190.2 5734.14,190.2 5774.14,190.2 9131.9,190.2 9171.9,190.2 9211.9,190.2 9251.9,190.2 9291.9,190.2 9331.9,190.2 9381.9,190.2 9421.9,190.2 9461.9,190.2 9501.9,190.2 9541.9,190.2 9581.9,190.2 4743.43,230.2 4783.43,230.2 4823.43,230.2 4863.43,230.2 4903.43,230.2 4943.43,230.2 4993.43,230.2 5033.43,230.2 5073.43,230.2 5113.43,230.2 5153.43,230.2 5193.43,230.2 5324.14,230.2 5364.14,230.2 5404.14,230.2 5444.14,230.2 5484.14,230.2 5524.14,230.2 5574.14,230.2 5614.14,230.2 5654.14,230.2 5694.14,230.2 5734.14,230.2 5774.14,230.2 9131.9,230.2 9171.9,230.2 9211.9,230.2 9251.9,230.2 9291.9,230.2 9331.9,230.2 9381.9,230.2 9421.9,230.2 9461.9,230.2 9501.9,230.2 9541.9,230.2 9581.9,230.2 4743.43,270.2 4783.43,270.2 4823.43,270.2 4863.43,270.2 4903.43,270.2 4943.43,270.2 4993.43,270.2 5033.43,270.2 5073.43,270.2 5113.43,270.2 5153.43,270.2 5193.43,270.2 5324.14,270.2 5364.14,270.2 5404.14,270.2 5444.14,270.2 5484.14,270.2 5524.14,270.2 5574.14,270.2 5614.14,270.2 5654.14,270.2 5694.14,270.2 5734.14,270.2 5774.14,270.2 9131.9,270.2 9171.9,270.2 9211.9,270.2 9251.9,270.2 9291.9,270.2 9331.9,270.2 9381.9,270.2 9421.9,270.2 9461.9,270.2 9501.9,270.2 9541.9,270.2 9581.9,270.2 4738.43,705.2 5198.43,705.2 5319.14,705.2 5779.14,705.2 9126.9,705.2 9586.9,705.2 4738.43,745.2 5198.43,745.2 5319.14,745.2 5779.14,745.2 9126.9,745.2 9586.9,745.2 4738.43,785.2 4778.43,785.2 4818.43,785.2 5118.43,785.2 5158.43,785.2 5198.43,785.2 5319.14,785.2 5359.14,785.2 5399.14,785.2 5699.14,785.2 5739.14,785.2 5779.14,785.2 9126.9,785.2 9166.9,785.2 9206.9,785.2 9506.9,785.2 9546.9,785.2 9586.9,785.2 5497.1,7033.1 5537.1,7033.1 5577.1,7033.1 5877.1,7033.1 5917.1,7033.1 5957.1,7033.1 5497.1,7073.1 5957.1,7073.1 5497.1,7113.1 5957.1,7113.1 5502.1,7548.1 5542.1,7548.1 5582.1,7548.1 5622.1,7548.1 5662.1,7548.1 5702.1,7548.1 5752.1,7548.1 5792.1,7548.1 5832.1,7548.1 5872.1,7548.1 5912.1,7548.1 5952.1,7548.1 5502.1,7588.1 5542.1,7588.1 5582.1,7588.1 5622.1,7588.1 5662.1,7588.1 5702.1,7588.1 5752.1,7588.1 5792.1,7588.1 5832.1,7588.1 5872.1,7588.1 5912.1,7588.1 5952.1,7588.1 5502.1,7628.1 5542.1,7628.1 5582.1,7628.1 5622.1,7628.1 5662.1,7628.1 5702.1,7628.1 5752.1,7628.1 5792.1,7628.1 5832.1,7628.1 5872.1,7628.1 5912.1,7628.1 5952.1,7628.1 5502.1,7668.1 5542.1,7668.1 5582.1,7668.1 5622.1,7668.1 5662.1,7668.1 5702.1,7668.1 5752.1,7668.1 5792.1,7668.1 5832.1,7668.1 5872.1,7668.1 5912.1,7668.1 5952.1,7668.1
  other v4: 9232.7,1304.4 9285.43,1369.87 2948.54,1434.8 9208.21,1550.51 3008.2,1701.8 9420.03,1757.2 2989.9,1851 9472.77,1885.9 8850.25,1904.31 3280.9,1924.85 2920.23,1926.46 3402.3,1933.73 3647.04,1944.27 9547.48,1950.06 3647.04,2077.27 3530.31,2272.73 5263.25,2715.4 5306.92,2715.4 5350.2,2715.4 5394.28,2715.4 5437.95,2715.4 6925.89,2746.04 5240.99,3261.09 5285.81,3261.09 5330.64,3261.09 5375.46,3261.09 5420.29,3261.09 5465.11,3261.09 6071.53,3261.09 6116.36,3261.09 6161.18,3261.09 6206.01,3261.09 6250.83,3261.09 6295.66,3261.09 6879.89,3260.69 6931.18,3260.69 6982.47,3260.69 7033.76,3260.69 7085.05,3260.69 7909.48,3290.77 7960.78,3290.77 8012.07,3290.77 8063.36,3290.77 8114.65,3290.77 5141.85,4376.28 5183.66,4376.28 5141.85,4415 5183.66,4415 5141.85,4453.71 5183.66,4453.71 5651.16,4607.84 5701.8,4607.84 6093.75,4631.15 5651.16,4647.19 5701.8,4647.19 5239.62,4671.06 6110.79,4674.6 5651.16,4686.55 5701.8,4686.55 5651.16,4725.9 5701.8,4725.9 5239.62,4730.11 6110.79,4733.65 5651.16,4765.26 5701.8,4765.26 5239.62,4799.01 6109.96,4799.01 5651.16,4804.61 5701.8,4804.61 7368.01,4864.55 7418.02,4865.39 7458.2,4938.5 7505.57,4938.5 8307.6,4952 8370.13,4952 7418.7,4968.59 8412.47,4982.77 7418.7,5011.11 7418.7,5053.64 7418.7,5096.17 7418.7,5138.7 8422.02,5161.64 7418.7,5181.23 8378.85,5201.53 7452.43,5215.1 7492.81,5215.1 7533.2,5215.1 5636.4,5220.75 5598.1,5221.73 5313.5,5229.53 6076.76,5229.53 6128.46,5229.53 5598.1,5274.01 5636.33,5274.01 6077.52,5287.54 6329.9,5296.54 5313.5,5304.5 6329.9,5363.2 5344.02,5560.58 5390.15,5560.58 5544.06,5560.58 5347.6,5746.46 5393.85,5746.46 5550.39,5764.4 6907.99,5766.95 6948.65,5766.95 6989.31,5766.95 5347.6,5783.2 5393.85,5783.2 6624.98,5818.43 6624.98,5866.73 6624.98,5915.03 6455.78,5921.94 9600.3,5938.5 9694.82,5938.5 9797.37,5938.5 9888.32,5938.5 6624.98,5963.33 6376.11,6005.7 6540.91,6007.8 6624.98,6011.63 6710.6,6071.09 7194.79,6071.91 7300.02,6071.91 5519.64,6106.43 6710.6,6112.41 5337.2,6113.16 5392.12,6113.16 5453.1,6113.16 7194.79,6113.39 7300.02,6113.39 5781.43,6130.7 6206.32,6137.77 5979.8,6165.5 6026.5,6165.5 6255.4,6181.79 530.6,6245.9 629.85,6245.9 729.1,6248.9 9597.8,6293.3 9692.32,6293.3 9794.87,6293.3 9885.82,6293.3 530.6,6329.2 629.85,6329.2 729.1,6331.2 9536.6,6348.9 9941.4,6348.9 530.6,6412.5 629.85,6412.5 729.1,6413.5 5937.66,6418.64 5989.94,6418.64 6040.33,6418.64 530.6,6495.8 629.85,6495.8 729.1,6495.8 5363.33,6497.55 5418.78,6497.55 5473.38,6497.55 360.1,6930.1 459.35,6930.1 558.6,6933.1 360.1,7013.4 459.35,7013.4 558.6,7015.4 360.1,7096.7 459.35,7096.7 558.6,7097.7 360.1,7180 459.35,7180 558.6,7180
  other v5: 5225.42,3966.37 5264.79,3966.37 5304.16,3966.37 5343.53,3966.37 5382.9,3966.37 5646.66,3966.37 5686.03,3966.37 5725.4,3966.37 5764.77,3966.37 5804.14,3966.37 6056.81,3966.37 6096.18,3966.37 6135.55,3966.37 6174.92,3966.37 6214.29,3966.37 6471.21,3966.37 6510.58,3966.37 6549.95,3966.37 6589.32,3966.37 6628.69,3966.37 6883.87,3966.37 6923.24,3966.37 6962.61,3966.37 7001.98,3966.37 7041.35,3966.37 7274.56,3966.37 7313.93,3966.37 7353.3,3966.37 7392.67,3966.37 7432.04,3966.37 7748.65,3965.98 7788.02,3965.98 7827.39,3965.98 7866.76,3965.98 7906.13,3965.98 8191.67,3966.69 8231.04,3966.69 8270.41,3966.69 8309.78,3966.69 8349.15,3966.69 7748.65,3999.44 7788.02,3999.44 7827.39,3999.44 7866.76,3999.44 7906.13,3999.44 5225.42,3999.83 5264.79,3999.83 5304.16,3999.83 5343.53,3999.83 5382.9,3999.83 5646.66,3999.83 5686.03,3999.83 5725.4,3999.83 5764.77,3999.83 5804.14,3999.83 6056.81,3999.83 6096.18,3999.83 6135.55,3999.83 6174.92,3999.83 6214.29,3999.83 6471.21,3999.83 6510.58,3999.83 6549.95,3999.83 6589.32,3999.83 6628.69,3999.83 6883.87,3999.83 6923.24,3999.83 6962.61,3999.83 7001.98,3999.83 7041.35,3999.83 7274.56,3999.83 7313.93,3999.83 7353.3,3999.83 7392.67,3999.83 7432.04,3999.83 8191.67,4000.15 8231.04,4000.15 8270.41,4000.15 8309.78,4000.15 8349.15,4000.15 5304.16,4033.3 5343.53,4033.3 5382.9,4033.3 5725.4,4033.3 5764.77,4033.3 5804.14,4033.3 6135.55,4033.3 6174.92,4033.3 6214.29,4033.3 6549.95,4033.3 6589.32,4033.3 6628.69,4033.3 6962.61,4033.3 7001.98,4033.3 7041.35,4033.3 7353.3,4033.3 7392.67,4033.3 7432.04,4033.3 7827.39,4032.9 7866.76,4032.9 7906.13,4032.9 8270.41,4033.62 8309.78,4033.62 8349.15,4033.62 7792.94,4064.4 5269.71,4064.79 5690.95,4064.79 6101.11,4064.79 6515.5,4064.79 6928.16,4064.79 7318.85,4064.79 8235.96,4065.11 5243.14,4095.31 5269.71,4095.31 5296.29,4095.31 5664.38,4095.31 5690.95,4095.31 5717.53,4095.31 6074.53,4095.31 6101.11,4095.31 6127.68,4095.31 6488.93,4095.3 6515.5,4095.3 6542.08,4095.3 6901.59,4095.3 6928.16,4095.3 6954.74,4095.3 7292.28,4095.3 7318.85,4095.3 7345.43,4095.3 7766.36,4094.91 7792.94,4094.91 7819.51,4094.91 8209.38,4095.62 8235.96,4095.62 8262.53,4095.62 7792.94,4125.42 5269.71,4125.82 5690.95,4125.82 6101.11,4125.82 6515.5,4125.82 6928.16,4125.82 7318.85,4125.82 8235.96,4126.14 6610.14,4686.1 6557.97,4738.26 6610.14,4738.26 6662.3,4738.26 6610.14,4790.43 7120.75,5103.08 7164.06,5103.08 5437.59,5221.73 5493.1,5221.73 5882.42,5229.53 5937.93,5229.53 5390.15,5274.01 5437.59,5274.01 5493.1,5274.01 5540.54,5274.01 6700.8,5281.36 6740.18,5281.36 6779.55,5281.36 6818.92,5281.36 5834.98,5281.81 5882.42,5281.81 5937.93,5281.81 5985.37,5281.81 6700.8,5320.73 6740.18,5320.73 6779.55,5320.73 5437.59,5326.3 5882.42,5334.1 6700.8,5360.1 6740.18,5360.1 6779.55,5360.1 6818.92,5360.1 7233.49,5553.08 7233.49,5582.6 7233.49,5612.13 5868.6,5630.01 5921.79,5630.01 5974.98,5630.01 5819.35,5679.26 5868.6,5679.26 5921.79,5679.26 5974.98,5679.26 6024.23,5679.26 5819.35,5732.45 5868.6,5732.45 5921.79,5732.45 5974.98,5732.45 6024.23,5732.45 5819.35,5785.64 5868.6,5785.64 5921.79,5785.64 5974.98,5785.64 6024.23,5785.64 5868.6,5834.89 5921.79,5834.89 5974.98,5834.89 6917.82,6059.03 6957.19,6059.03 6996.56,6059.03 7506.27,6059.03 7545.64,6059.03 7585.01,6059.03 6917.82,6098.4 6957.19,6098.4 6996.56,6098.4 7506.27,6098.4 7545.64,6098.4 7585.01,6098.4 6917.82,6137.77 6957.19,6137.77 6996.56,6137.77 7506.27,6137.77 7545.64,6137.77 7585.01,6137.77 6917.82,6177.14 6957.19,6177.14 6996.56,6177.14 7506.27,6177.14 7585.01,6177.14 5993.26,6213.97 5940.98,6261.41 5993.26,6261.41 6045.54,6261.41 5940.98,6316.93 5993.26,6316.93 6045.54,6316.93 5993.26,6364.37
GPO1: J4.1 R223.2 TP73.1 U16.16 | length 3684
  Top Layer w6: TP73.1@3121.11,7210.8 3226.2,7210.8 3267.2,7169.8 J4.1@3385.2,7169.8 ; v2(5774.34,5888.83) 5777.59,5888.83 5782.31,5884.1 5802.81,5884.1 5802.89,5884.02 U16.16@5803.68,5884.02
  Signal 1 w6: v2(5683.55,5923.62) 5768.01,5923.62 5774.34,5917.29 v2(5774.34,5888.83)
  Singal 3 w6: J4.1@3385.2,7169.8 3462.56,7169.8 3539.28,7093.07 3588.5,7043.86 3588.5,6417.66 3614.46,6391.7 4723.96,6391.7 5079.16,6036.5 5474.59,6036.5 5587.48,5923.62 v2(5683.55,5923.62)
  Bottom Layer w6: R223.2@5645.99,5958.66 5645.99,5930.82 5653.19,5923.62 v2(5683.55,5923.62)
GPO2: J4.2 R224.2 TP75.1 U16.26 | length 3977.2
  Top Layer w6: TP75.1@3120.11,7091.8 3245.2,7091.8 3267.2,7069.8 J4.2@3385.2,7069.8 ; v2(5704.39,5698.16) 5707.64,5698.16 5718.31,5708.83 U16.26@5770.22,5708.83
  Singal 3 w6: J4.2@3385.2,7069.8 3547,7069.8 3577.5,7039.3 3577.5,6413.1 3609.9,6380.7 4719.4,6380.7 5015.3,6084.8 5216.3,5883.8 5216.3,5586.54 5273.14,5529.7 5561.01,5529.7 5673.96,5642.65 5673.96,5686.3 5685.82,5698.16 v2(5704.39,5698.16)
  Bottom Layer w6: R224.2@5665.69,5696.61 5667.23,5698.16 v2(5704.39,5698.16)
GPO3: J4.3 R222.2 TP72.1 U16.27 | length 3866.9
  Top Layer w6: TP72.1@3121.11,6966.8 3261.4,6966.8 3264.4,6969.8 J4.3@3385.2,6969.8 ; v2(5694.3,5674.94) 5695.64,5676.29 5712.3,5676.29 5729.09,5693.08 U16.27@5770.22,5693.08
  Singal 3 w6: J4.3@3385.2,6969.8 3539,6969.8 3566.5,6942.3 3566.5,6408.54 3605.34,6369.7 4714.84,6369.7 5205.3,5879.24 5205.3,5581.98 5268.58,5518.7 5565.57,5518.7 5684.96,5638.1 5684.96,5662.36 5694.3,5671.7 v2(5694.3,5674.94)
  Bottom Layer w6: R222.2@5665.69,5656.6 5682.94,5656.6 5687.19,5660.84 5687.19,5664.58 5694.3,5671.7 v2(5694.3,5674.94)
GPO4: J4.4 R225.2 TP76.1 U16.28 | length 3796.4
  Top Layer w6: TP76.1@3120.11,6838.8 3257.85,6838.8 3288.85,6869.8 J4.4@3385.2,6869.8 ; v2(5707.96,5656.44) 5728.9,5677.33 U16.28@5770.22,5677.33
  Singal 3 w6: J4.4@3385.2,6869.8 3516.3,6869.8 3555.5,6830.6 3555.5,6403.99 3600.79,6358.7 4710.29,6358.7 5194.3,5874.69 5194.3,5577.43 5248.8,5522.93 5264.03,5507.7 5570.12,5507.7 5706.59,5644.17 5706.59,5655.07 v2(5707.96,5656.44)
  Bottom Layer w6: R225.2@5665.69,5616.59 5684.79,5616.59 5706.59,5638.39 5706.59,5655.07 v2(5707.96,5656.44)
IIN-CSN: C20.2 C25.1 R28.1 R29.2 R38.2 U3.38 | length 1806.6
  Top Layer w6: U3.38@6704.62,4777.63 6749.52,4777.63 v2(6762.45,4764.71)
  Signal 1 w6: v2(6762.45,4764.71) 6849.49,4764.71 6880.87,4796.1 7414.4,4796.1 7562.8,4944.5 v2(7562.8,5545.4)
  Bottom Layer w6: v2(7562.8,5545.4) 7563.4,5546 C20.2@7603.5,5546 7662.2,5546 7714.1,5546 R28.1@7714.7,5545.4 7775.61,5545.4 R29.2@7775.91,5545.7 7775.91,5492.41 R38.2@7775.4,5491.9
IIN-CSP: C19.1 C20.1 R24.2 R26.2 R28.2 U3.37 | length 1912
  Top Layer w6: U3.37@6704.62,4761.89 6734.39,4761.89 6752.38,4743.9 v2(6783.26,4743.9)
  Signal 1 w6: v2(6783.26,4743.9) 6854.28,4743.9 6895.48,4785.1 7450.68,4785.1 7585.01,4919.43 7585.01,5581.99 v2(7562.8,5604.2)
  Bottom Layer w6: v2(7562.8,5604.2) 7601.7,5604.2 C20.1@7603.5,5606 7714.1,5606 R28.2@7714.7,5605.4 7775.6,5605.4 R26.2@7775.91,5605.71 R24.2@7775.91,5649.02
ILIM1: R212.1 U16.30 | length 99.3
  Top Layer w6: v2(5724.66,5616.59) 5753.9,5645.84 U16.30@5770.22,5645.84
  Bottom Layer w6: R212.1@5704.7,5583.21 5704.7,5596.63 v2(5724.66,5616.59)
ILIM2: R213.1 U16.64 | length 94.2
  Top Layer w6: U16.64@6073.37,5850.56 6073.37,5886.33 6105.45,5918.41 6105.45,5931.22 R213.1@6105.63,5931.4
ILIM6: R211.1 U16.45 | length 103.2
  Top Layer w6: U16.45@5992.66,5580.87 5992.66,5556.46 6003.18,5545.94 6003.18,5528.99 v2@6004.23,5527.94
  Bottom Layer w6: R211.1@5979.8,5554.2 5998,5554.2 6001.52,5550.69 v2(6001.52,5528.42)
IOUT1: J32.2 R151.1 U8.38 | length 3707.4
  Top Layer w6: v2(5217.21,4187.04) 5217.9,4187.74 5239.62,4187.74 5243.14,4184.22 U8.38@5243.14,4159.28 ; v2@6518.75,4496.1 6518.65,4496.2 6518.65,4525.9 R151.1@6518.95,4526.2
  Power 2 w6: v2(5217.21,4187.04) 5217.21,4219.33 5247.57,4249.7 5664.13,4249.7 5776.9,4362.46 6260.27,4362.46 6311.84,4414.03 6472.66,4414.03 6492.86,4434.23 6518.65,4460.02 v2(6518.65,4495.3)
  Power 3 w6: J32.2@3995.7,2839.5 4243.94,2839.5 4931.1,3526.66 4931.1,4104.16 5059.68,4232.74 5171.51,4232.74 v2(5217.21,4187.04)
IOUT2: J38.2 R160.1 U9.38 | length 3697.3
  Top Layer w6: v2(5632.82,4187.74) 5660.87,4187.74 5664.38,4184.22 U9.38@5664.38,4159.28 ; R160.1@6556.35,4526 6557.95,4524.4 v2(6557.95,4495.3)
  Power 2 w6: v2(5632.82,4187.74) 5672.58,4187.74 5716.13,4231.29 5783.49,4231.29 5842.15,4289.95 5958.53,4289.95 5998.45,4329.87 6449.17,4329.87 6557.95,4438.65 v2(6557.95,4495.3)
  Power 3 w6: J38.2@3995.7,2973.7 4307.14,2973.7 4888.3,3554.86 4888.3,4112.42 5030.78,4254.9 5565.66,4254.9 5576.66,4243.9 v2(5632.82,4187.74)
IOUT3: J39.2 R168.1 U10.38 | length 3815.5
  Top Layer w6: v2(6042.47,4194.16) 6061.63,4194.16 6074.17,4181.62 6074.17,4163.24 U10.38@6074.53,4162.88 ; R168.1@6596.35,4524.4 6596.95,4523.8 v2(6596.95,4495.3)
  Power 2 w6: v2(6042.47,4194.16) 6089.43,4241.12 6364.06,4241.12 6372.64,4249.7 6393.85,4249.7 6475.46,4331.31 6528.57,4331.31 6596.95,4399.7 v2(6596.95,4495.3)
  Power 3 w6: J39.2@3995.7,3107.9 4367.64,3107.9 4774.1,3514.36 4774.1,4063.26 5038.94,4328.1 5599.55,4328.1 5645.95,4374.5 5909.03,4374.5 6042.47,4241.06 v2(6042.47,4194.16)
IOUT4: J40.2 R175.1 U11.38 | length 4519.5
  Top Layer w6: v2(6447.74,4190.95) 6480.9,4190.95 6488.93,4182.93 U11.38@6488.93,4168.66 ; v2(6635.45,4495.3) 6635.45,4524.6 R175.1@6635.65,4524.8
  Power 2 w6: v2(6447.74,4190.95) 6527.81,4190.95 6635.45,4298.59 v2(6635.45,4495.3)
  Power 3 w6: v2(6447.74,4190.95) 6448.32,4191.54 6448.32,4245.2 6422.85,4270.67 6422.85,4303.12 6535.37,4415.64 10168.64,4415.64 J40.2@10230,4477
IOUT5: J41.2 R184.1 U12.38 | length 4099.2
  Top Layer w6: R184.1@6674.85,4527.2 6675.65,4526.4 6675.65,4473.77 v2(6688.7,4460.73) ; v2(6859.88,4199.51) 6893.93,4199.51 6901.59,4191.85 U12.38@6901.59,4167.23
  Power 2 w6: v2(6688.7,4460.73) 6688.7,4386.77 6859.88,4215.59 v2(6859.88,4199.51)
  Power 3 w6: v2(6859.88,4199.51) 6871.1,4210.73 6871.1,4348.1 6914.33,4391.33 10063.89,4391.33 10077.74,4377.48 10077.74,4310.14 10087.71,4300.17 10186.17,4300.17 J41.2@10230,4344
IOUT6: J42.2 R192.1 U13.38 | length 4070.4
  Top Layer w6: v2(6713.45,4495.3) 6713.45,4525 R192.1@6714.45,4526 ; v2(7248.83,4200.75) 7251.13,4198.45 7265.64,4198.45 7271.87,4192.23 7279.9,4192.23 7292.23,4179.9 7292.23,4160.53 U13.38@7292.28,4160.48
  Power 2 w6: v2(6713.45,4495.3) 6713.45,4493.94 6721.61,4485.79 6721.61,4454.76 6920.12,4256.25 7198.83,4256.25 7222.68,4232.4 7222.68,4226.9 v2(7248.83,4200.75)
  Power 3 w6: v2(7248.83,4200.75) 7212.49,4237.09 7212.49,4337.19 7244.64,4369.33 9723.67,4369.33 9898.1,4194.9 10061.8,4194.9 10096.9,4159.8 10183.9,4159.8 J42.2@10230,4205.9
IRQB: J23.6 J29.2 TP70.1 U16.15 | length 4301.7
  Top Layer w6: J23.6@2608.49,7508.58 2608.49,7414.71 2633.2,7390 2740.5,7390 J29.2@2796.5,7334 3119.58,7334 TP70.1@3120.11,7333.46 ; TP70.1@3120.11,7332.8 v2(3245.2,7332.8) ; v2(5815.15,5906.79) 5815.15,5905.16 5819.07,5901.24 5819.07,5884.38 U16.15@5819.43,5884.02
  Singal 3 w6: v2(3245.2,7332.8) 3315.11,7332.8 3599.5,7048.41 3599.5,6447 3643.8,6402.7 4728.51,6402.7 5083.71,6047.5 5479.15,6047.5 5562.44,5964.21 5676.81,5964.21 5724.16,5916.87 5805.07,5916.87 v2(5815.15,5906.79)
LDO3P3: C350.1 R215.2 R216.2 R217.2 R218.2 R219.2 R220.2 R221.1 R222.1 R223.1 R224.1 R225.1 R226.2 R227.2 U16.54 | length 699.2
  Top Layer w6: U16.54@6073.37,5693.08 6111.07,5693.08 6115.82,5697.83 6127.22,5697.83 v2(6128.7,5699.31)
  Bottom Layer w6: R223.1@5685.99,5958.66 5702.36,5958.66 5708.57,5952.44 5709.06,5952.93 5720.28,5952.93 v2(5722.57,5955.23) R220.2@5748.83,5955.23 R216.2@5748.84,5912.95
  Bottom Layer w10: R224.1@5625.69,5696.61 R222.1@5625.69,5656.6 5625.69,5596.25 5645.54,5576.4 v2(5671.6,5576.4) ; v2(6128.7,5699.31) 6138.3,5689.71 C350.1@6162.51,5689.71 6162.85,5690.05 6182.89,5690.05 6214.8,5721.96 R226.2@6214.8,5759.5 R227.2@6214.8,5799 R219.2@6214.8,5838.49 R218.2@6214.8,5877.99 R217.2@6214.8,5917.48 R221.1@6214.8,5956.98 R215.2@6214.8,5996.47
LDO5V0: C337.1 C338.1 C351.1 U16.8 U16.38 U16.56 | length 339.6
  Top Layer w6: U16.8@5929.66,5884.02 5929.31,5884.38 5929.63,5884.71 v2(5929.6,5914.4) ; U16.56@6073.37,5724.58 6107.83,5724.58 6112.55,5729.29 6150.75,5729.29 6159.68,5720.36 6172.79,5720.36 v2(6172.96,5720.18) 6173.71,5720.93 6190.96,5720.93 6193.96,5723.93 C351.1@6211.96,5723.93
  Top Layer w8: v2(5882.42,5527.94) U16.38@5882.42,5580.87
  Bottom Layer w6: v2(5882.42,5527.94) C337.1@5882.42,5552.02 ; v2(5929.6,5914.4) 5929.6,5931.12 5949.32,5950.84 C338.1@5949.32,5992.24
LDOA1: C353.1 J1.2 U16.9 | length 122.9
  Top Layer w6: U16.9@5913.92,5884.02 5913.92,5913.91 5912.66,5915.16 5912.66,5941.84 v2(5925.73,5954.9)
  Bottom Layer w6: C353.1@5900.72,5990.65 5901.42,5989.95 5901.42,5979.2 v2(5925.73,5954.9)
LDOA2: C354.1 J1.3 U16.51 | length 115
  Top Layer w6: U16.51@6073.37,5645.84 6073.72,5645.48 6089.91,5645.48 6097.69,5637.7 6108.8,5637.7 6123.74,5622.76 v2(6153.37,5622.76) 6178.54,5622.76 C354.1@6178.7,5622.6
LDOA3: C355.1 J1.1 U16.49 | length 67.3
  Top Layer w6: U16.49@6073.37,5614.34 6073.37,5601.4 6078.88,5595.89 6089.33,5595.89 v2(6091.63,5593.59)
  Bottom Layer w6: v2(6091.63,5593.59) 6102.25,5582.97 C355.1@6102.25,5565.14
LX3: L13.1 U16.10
LX4: L14.1 U16.25
LX5: L15.1 U16.20
MODE1-U1: R230.1 R231.1 U17.37 | length 80.6
  Top Layer w6: U17.37@7059.62,6237.02 7060.71,6238.12 7079.48,6238.12 7085.68,6244.32 7100.98,6244.32 R230.1@7103.98,6247.32 7104.28,6247.02 7135.43,6247.02 R231.1@7135.74,6246.71
MODE1-U3: R235.2 R237.1 U18.37 | length 94.9
  Top Layer w6: U18.37@6877.97,5218.37 6879.89,5216.45 6879.89,5198.65 6906.76,5171.77 R235.2@6907.55,5171.77 R237.1@6907.55,5136.14
MODE1-U4: R242.2 R244.1 U19.37 | length 80.2
  Top Layer w6: U19.37@7648,6236.2 7667.1,6236.2 7672.25,6241.35 7718.81,6241.35 7723.39,6236.77 R244.1@7724.18,6236.77
MODE2-U1: R230.2 R232.1 U17.38 | length 86.8
  Top Layer w6: 7058.92,6256.22 7072.06,6269.37 R230.2@7103.98,6269.37 ; R230.2@7102.22,6270.02 7103.85,6270.02 7110.44,6276.62 R232.1@7135.74,6276.62
MODE2-U3: R235.1 R238.1 U18.38 | length 109.8
  Top Layer w6: U18.38@6900.12,5229.69 6900.12,5212.2 6928.76,5183.56 6928.76,5172.61 R235.1@6929.6,5171.77 6930.39,5171.77 6933.68,5168.48 6933.68,5167.69 6938.26,5163.11 R238.1@6938.26,5136.14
